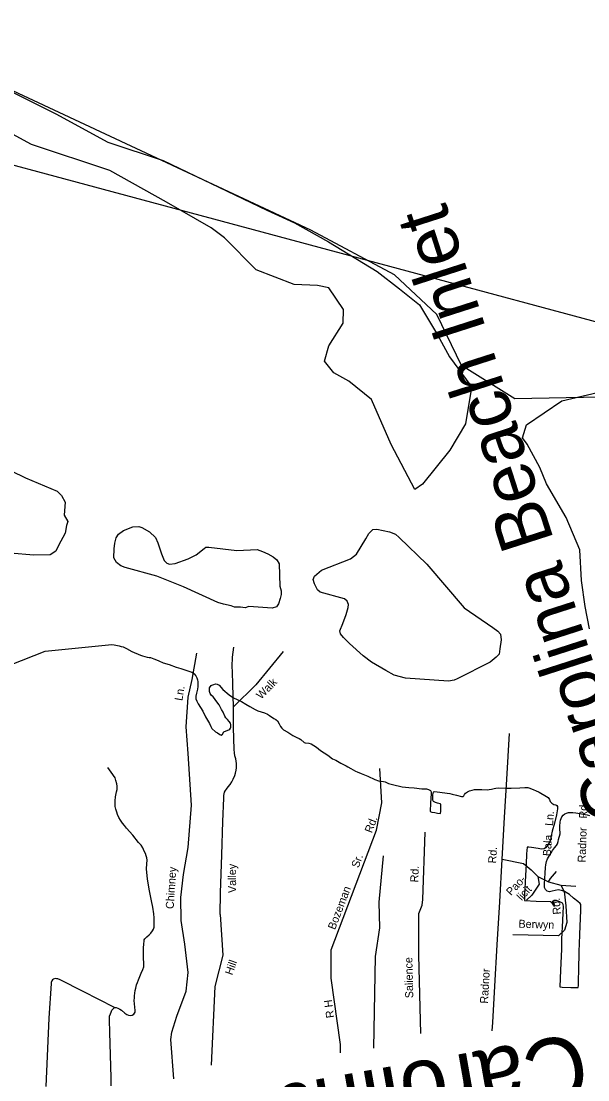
# Model space of a CAD drawing. Extents: x 2308163 to 2335412, y -96774 to 125428.
# Drawn here: x 2326217.9 to 2326312.3, y 123164.6 to 123340.9 of the extents above; entities that cross this region are included whole.
import ezdxf

# ---------------------------------------------------------------- set-up
doc = ezdxf.new("R2010")
doc.units = 0
for name, color, linetype in [('Old_Level_10', 7, 'Continuous'), ('Old_Level_21', 7, 'Continuous'), ('Old_Level_35', 7, 'Continuous'), ('Old_Level_52', 7, 'Continuous'), ('Old_Level_6', 7, 'Continuous'), ('Old_Level_60', 7, 'Continuous'), ('Old_Level_61', 7, 'Continuous'), ('Old_Level_63', 7, 'Continuous')]:
    doc.layers.add(name, color=color, linetype=linetype)

msp = doc.modelspace()

# ---------------------------------------------------------------- linework, layer by layer
at = {"layer": 'Old_Level_35'}
for p, q in [((2326271.09, 123170.5), (2326269.51, 123181.52)), ((2326296.37, 123172.76), (2326296.45, 123174.17)), ((2326271.09, 123169.11), (2326271.09, 123170.5)), ((2326232.91, 123163.62), (2326232.87, 123165))]:
    msp.add_line(p, q, dxfattribs=at)
for points in [[(2326246.36, 123231.28), (2326247.13, 123235.68)], [(2326253.29, 123226.74), (2326253.14, 123230.41), (2326253.07, 123232.56), (2326253.04, 123233.45), (2326253.08, 123234.96), (2326253.33, 123236.66)], [(2326261.52, 123235.93), (2326256.96, 123230.39), (2326253.29, 123226.74)], [(2326243.33, 123164.79), (2326242.85, 123171.32), (2326242.99, 123172.56), (2326243.81, 123175.21), (2326245.39, 123179.38), (2326245.71, 123182.46), (2326245.15, 123187.22), (2326244.56, 123191.15), (2326244.49, 123194.97), (2326244.93, 123198.77), (2326245.7, 123203.27), (2326246.26, 123210.36), (2326245.73, 123218.94), (2326245.36, 123223.38), (2326245.74, 123228.31), (2326246.36, 123231.28)], [(2326251.03, 123192.12), (2326251.12, 123195.74), (2326251.32, 123202.08), (2326251.49, 123207.64), (2326251.67, 123211.49), (2326251.67, 123211.95), (2326251.7, 123212.22), (2326251.77, 123212.51), (2326251.94, 123212.79), (2326252.12, 123213.03), (2326252.4, 123213.39), (2326252.7, 123213.79), (2326252.98, 123214.22), (2326253.21, 123214.66), (2326253.46, 123215.27), (2326253.59, 123215.68), (2326253.7, 123216.15), (2326253.76, 123216.57), (2326253.76, 123216.91), (2326253.76, 123217.26), (2326253.7, 123217.69), (2326253.63, 123218.03), (2326253.5, 123218.58), (2326253.43, 123219.07), (2326253.37, 123219.63), (2326253.29, 123223.25), (2326253.29, 123226.74)], [(2326296.45, 123174.17), (2326296.8, 123180.2), (2326297.2, 123187.11), (2326297.63, 123194.25), (2326298.04, 123201.35), (2326298.41, 123208.29), (2326298.81, 123214.66), (2326299.23, 123222.26)], [(2326233.42, 123176.66), (2326233.54, 123176.66), (2326233.71, 123176.66), (2326233.99, 123176.56), (2326234.35, 123176.39), (2326234.59, 123176.18), (2326235.19, 123175.72), (2326235.51, 123175.51), (2326235.77, 123175.37), (2326236.1, 123175.34), (2326236.4, 123175.36), (2326236.65, 123175.53), (2326236.77, 123175.68), (2326236.86, 123175.89), (2326236.91, 123176.13), (2326236.74, 123177.84), (2326236.75, 123178.28), (2326236.76, 123178.61), (2326236.91, 123179.46), (2326237, 123179.86), (2326237.13, 123180.43), (2326237.27, 123180.83), (2326237.44, 123181.28), (2326237.65, 123181.8), (2326237.9, 123182.35), (2326238.17, 123182.97), (2326238.31, 123183.41), (2326238.35, 123183.77), (2326238.32, 123184.1), (2326238.3, 123184.79), (2326238.27, 123185.53), (2326238.3, 123186.5), (2326238.32, 123187.31), (2326238.36, 123187.63), (2326238.4, 123187.89), (2326238.51, 123188.1), (2326238.83, 123188.43), (2326239.2, 123188.75), (2326239.5, 123189.03), (2326239.75, 123189.39), (2326239.93, 123189.72), (2326240.03, 123190.05), (2326240.06, 123190.48), (2326240.07, 123190.92), (2326240.04, 123191.58), (2326239.98, 123192.23), (2326239.81, 123193.37), (2326239.58, 123194.43), (2326239.3, 123196.06), (2326238.94, 123198.03), (2326238.86, 123198.65), (2326238.81, 123199.13), (2326238.79, 123199.74), (2326238.84, 123200.58), (2326238.86, 123201.2), (2326238.82, 123201.56), (2326238.71, 123201.93), (2326238.58, 123202.27), (2326238.4, 123202.67), (2326238.14, 123203.21), (2326237.86, 123203.66), (2326237.46, 123204.15), (2326236.52, 123205.36), (2326235.45, 123206.52), (2326235.09, 123206.93), (2326234.78, 123207.35), (2326234.43, 123207.84), (2326234.18, 123208.28), (2326233.95, 123208.77), (2326233.81, 123209.16), (2326233.66, 123209.69), (2326233.58, 123210.14), (2326233.55, 123210.47), (2326233.55, 123211.08), (2326233.62, 123211.73), (2326233.8, 123212.54), (2326233.88, 123212.94), (2326233.9, 123213.48), (2326233.84, 123213.88), (2326233.69, 123214.45), (2326233.54, 123214.9), (2326232.87, 123215.81), (2326232.32, 123216.59)], [(2326269.51, 123181.52), (2326269.55, 123186.23), (2326277.06, 123206.18), (2326277.96, 123210.73), (2326277.66, 123216.44)], [(2326284.45, 123172.32), (2326284.14, 123185.35), (2326284.15, 123192.28), (2326284.66, 123193.67), (2326284.81, 123194.66), (2326285.2, 123205.85)], [(2326276.64, 123169.9), (2326276.91, 123185.13), (2326277.61, 123189.92), (2326277.52, 123194.21), (2326278.25, 123201.93)], [(2326298.04, 123201.35), (2326301.59, 123200.65), (2326302.84, 123199.55), (2326303.98, 123198.46), (2326304.17, 123197.16), (2326302.93, 123195.33), (2326302.08, 123194.53)], [(2326303.98, 123198.46), (2326305.71, 123197.58), (2326306.08, 123198.15), (2326307.04, 123199.31)], [(2326307.81, 123197.04), (2326308.36, 123195.96), (2326308.63, 123193.6), (2326308.77, 123190.78), (2326308.37, 123189.51), (2326307.4, 123188.6), (2326299.77, 123188.75)], [(2326305.71, 123197.58), (2326307.81, 123197.04), (2326310.27, 123196.83)], [(2326251.03, 123192.12), (2326251.48, 123185.35), (2326250.16, 123180.14), (2326249.56, 123167.05)], [(2326233.42, 123176.66), (2326228.25, 123179.34), (2326224.39, 123181.23), (2326223.99, 123181.4), (2326223.79, 123181.44), (2326223.55, 123181.46), (2326223.31, 123181.39), (2326223.13, 123181.25), (2326223.01, 123181.09), (2326222.91, 123180.83), (2326222.91, 123180.65), (2326222.49, 123174.89), (2326222.02, 123163.5)], [(2326232.87, 123165), (2326232.67, 123172.49), (2326232.6, 123174.57), (2326232.61, 123174.93), (2326232.63, 123175.23), (2326232.75, 123175.62), (2326232.87, 123175.9), (2326233.01, 123176.18), (2326233.42, 123176.66)]]:
    msp.add_lwpolyline(points, dxfattribs=at)
at = {"layer": 'Old_Level_52'}
msp.add_lwpolyline([(2326352.46, 123278.37), (2326344.49, 123279.39), (2326334.11, 123277.47), (2326314.41, 123278.3), (2326300.12, 123278.02), (2326291.22, 123283.57), (2326287.11, 123292.06), (2326280.06, 123298.67), (2326266.15, 123306.08), (2326194.23, 123339.67), (2326117.56, 123374.58), (2325996.97, 123429.09), (2325967.84, 123440.3), (2325941.49, 123450.31)], dxfattribs=at)
at = {"layer": 'Old_Level_60'}
for points in [[(2326127.66, 123373.96), (2326132.4, 123371.8), (2326136.14, 123367.53), (2326140.13, 123366.07), (2326143.93, 123363.85), (2326143.86, 123361.92), (2326157.43, 123357.03), (2326182.68, 123345.67), (2326202.81, 123335.85), (2326223.69, 123325.46), (2326232.34, 123320.74), (2326241.56, 123317.67)], [(2326242.1, 123310.74), (2326232.69, 123316.04), (2326219.63, 123320.35), (2326204.37, 123328.62), (2326193.35, 123332.04), (2326192.88, 123333.43), (2326189.59, 123335.76), (2326186.26, 123336.7), (2326182.89, 123336.82), (2326179.29, 123337.5), (2326177.6, 123341.14)], [(2326241.56, 123317.67), (2326258.84, 123309.4), (2326263.45, 123307.33), (2326269.08, 123304.16), (2326277.2, 123299.21), (2326280.93, 123296.32), (2326284.24, 123293.65), (2326287.26, 123288.66), (2326289.26, 123284.98), (2326292.81, 123280.16)], [(2326292.81, 123280.16), (2326292.91, 123279.91), (2326291.88, 123273.83), (2326289.28, 123269.43), (2326284.76, 123263.8), (2326283.44, 123262.88), (2326279.52, 123270.41), (2326276.24, 123277.92), (2326272.49, 123280.95), (2326269.96, 123282.32), (2326268.42, 123284.3), (2326269.15, 123286.85), (2326271.53, 123290.63), (2326271.61, 123292.88), (2326269.16, 123296.5), (2326267.24, 123296.89), (2326263.39, 123297.02), (2326257.04, 123299.49), (2326251.75, 123304.82), (2326249.56, 123306.5), (2326242.1, 123310.74)], [(2326302.05, 123273.67), (2326307.94, 123277.66), (2326313.91, 123279.08), (2326320.04, 123279.28), (2326325.92, 123277.85), (2326333.48, 123278), (2326338.39, 123278.44), (2326343.96, 123279.89), (2326346.61, 123279.79), (2326350.86, 123278.63), (2326397.35, 123255.76)], [(2326312.56, 123239.69), (2326311.86, 123243.45), (2326311.2, 123247.75), (2326310.96, 123252.86), (2326308.7, 123258.25), (2326305.42, 123263.87), (2326304.29, 123266.56), (2326302.18, 123270.47), (2326301.39, 123271.53), (2326302.05, 123273.67)], [(2326216.12, 123233.73), (2326221.9, 123236.01), (2326233, 123237.09), (2326233.41, 123237.03), (2326234.21, 123236.87), (2326234.57, 123236.78), (2326234.89, 123236.68), (2326235.46, 123236.44), (2326236.34, 123235.92), (2326237.79, 123235.3), (2326238.1, 123235.2), (2326238.89, 123234.98), (2326239.2, 123234.92), (2326239.43, 123234.91), (2326240.02, 123234.73), (2326240.42, 123234.55), (2326240.8, 123234.35), (2326241.53, 123234.05), (2326242.56, 123233.74), (2326243.73, 123233.32), (2326244.48, 123233.12), (2326245.31, 123232.83), (2326245.68, 123232.73), (2326246.31, 123232.49), (2326246.48, 123232.4), (2326246.72, 123232.19), (2326246.97, 123231.86), (2326247.13, 123231.54), (2326247.26, 123231.19), (2326247.31, 123230.89), (2326247.3, 123230.1), (2326247.25, 123229.64), (2326247.1, 123229.01), (2326247.01, 123228.48), (2326246.99, 123228.05), (2326247.15, 123227.64), (2326247.39, 123227.21), (2326248.13, 123225.97), (2326248.59, 123225.07), (2326249.29, 123223.92), (2326249.49, 123223.45), (2326249.68, 123223.09), (2326250.29, 123222.54), (2326250.62, 123222.36), (2326250.97, 123222.12), (2326251.22, 123222.01), (2326251.41, 123222.19)], [(2326251.41, 123222.19), (2326251.67, 123222.53), (2326252.04, 123222.73), (2326252.46, 123222.89), (2326252.64, 123223), (2326252.77, 123223.16), (2326252.83, 123223.31), (2326252.82, 123223.71), (2326252.74, 123224.02), (2326252.53, 123224.3), (2326252.26, 123224.6), (2326252.01, 123224.91), (2326251.84, 123225.18), (2326251.54, 123225.84), (2326251.29, 123226.26), (2326250.85, 123227.07), (2326250.32, 123227.76), (2326250.11, 123228.08), (2326249.86, 123228.39), (2326249.57, 123228.68), (2326249.35, 123228.93), (2326249.25, 123229.28), (2326249.24, 123229.59), (2326249.28, 123229.87), (2326249.57, 123230.29), (2326249.65, 123230.34), (2326249.96, 123230.46), (2326250.26, 123230.52), (2326250.57, 123230.47), (2326250.87, 123230.31), (2326251.48, 123229.63), (2326252.53, 123228.71), (2326252.91, 123228.43), (2326253.28, 123228.2), (2326254.57, 123227.62), (2326255.31, 123227.16), (2326255.99, 123226.78), (2326256.85, 123226.27), (2326257.3, 123226.07), (2326258.44, 123225.72), (2326258.92, 123225.48), (2326259.28, 123225.26), (2326259.97, 123224.78), (2326260.31, 123224.58), (2326260.61, 123224.37), (2326260.87, 123223.88), (2326261.07, 123223.45), (2326261.3, 123223.17), (2326261.6, 123222.9), (2326262.3, 123222.49), (2326263.16, 123221.95), (2326263.82, 123221.61), (2326264.18, 123221.45), (2326264.48, 123221.29), (2326265.03, 123220.77), (2326265.19, 123220.7), (2326265.79, 123220.66), (2326266.21, 123220.53), (2326266.67, 123220.29), (2326267.07, 123220), (2326267.74, 123219.46), (2326268.95, 123218.65), (2326269.75, 123218.07), (2326270.29, 123217.81), (2326271.12, 123217.32), (2326272.01, 123216.88), (2326272.33, 123216.74), (2326272.81, 123216.47), (2326273.56, 123216.01), (2326273.84, 123215.87), (2326274.5, 123215.63), (2326275.64, 123215.17), (2326276.8, 123214.63), (2326277.43, 123214.42), (2326277.84, 123214.33), (2326278.22, 123214.29), (2326278.5, 123214.23), (2326279.06, 123213.96), (2326279.74, 123213.76), (2326281.38, 123213.42), (2326282.48, 123213.29), (2326283.37, 123213.23), (2326284.65, 123213.07), (2326285.41, 123213.04), (2326285.77, 123212.94), (2326286.06, 123212.78), (2326286.16, 123212.58), (2326286.17, 123212.23), (2326286.06, 123210.71), (2326286.01, 123209.29), (2326286.31, 123209.17), (2326286.81, 123209.11), (2326287.25, 123209), (2326287.73, 123208.95), (2326287.77, 123209.33), (2326287.79, 123210.18), (2326287.78, 123210.5), (2326287.69, 123210.56), (2326287.23, 123210.67)], [(2326287.23, 123210.67), (2326286.91, 123210.77), (2326286.55, 123210.96), (2326286.47, 123211.17), (2326286.47, 123211.59), (2326286.49, 123212.06), (2326286.58, 123212.53), (2326286.7, 123212.62), (2326287.19, 123212.58), (2326289.27, 123212.28), (2326289.68, 123212.19), (2326290.39, 123211.99), (2326291.22, 123211.79), (2326291.53, 123211.8), (2326291.64, 123211.92), (2326291.72, 123212.12), (2326291.92, 123212.35), (2326292.23, 123212.57), (2326292.59, 123212.73), (2326292.99, 123212.85), (2326293.39, 123212.94), (2326293.79, 123212.97), (2326294.63, 123212.97), (2326295.54, 123212.9), (2326295.86, 123212.93), (2326296.22, 123213.03), (2326296.67, 123213.12), (2326296.98, 123213.2), (2326297.45, 123213.23), (2326298.69, 123213.15), (2326299.51, 123213.17), (2326300.97, 123213.23), (2326301.79, 123213.31), (2326302.26, 123213.29), (2326302.64, 123213.18), (2326303.27, 123212.9), (2326303.56, 123212.76), (2326304.2, 123212.49), (2326305.39, 123211.8), (2326305.65, 123211.61), (2326305.88, 123211.31), (2326306.02, 123210.97), (2326306.28, 123210.69), (2326306.63, 123210.48), (2326306.97, 123210.38), (2326307.14, 123210.3), (2326307.24, 123210.11), (2326307.24, 123209.75), (2326307.08, 123208.74), (2326306.74, 123207.35), (2326306.36, 123206.01), (2326306.17, 123205.21), (2326306.05, 123204.55), (2326305.93, 123204.22), (2326305.72, 123203.89)], [(2326305.72, 123203.89), (2326305.22, 123203.22), (2326305.02, 123203.05), (2326304.54, 123203.04), (2326304.02, 123203.1), (2326302.9, 123203.28), (2326302.44, 123203.33), (2326302.17, 123203.34), (2326302.1, 123202.82), (2326302.05, 123202.26), (2326302, 123200.52), (2326301.92, 123198.64), (2326301.85, 123197.5), (2326301.81, 123196.41), (2326301.76, 123195.46), (2326301.73, 123194.47), (2326303.68, 123194.34), (2326306.06, 123194.28), (2326306.21, 123194.21), (2326306.57, 123193.63), (2326306.64, 123193.55), (2326306.81, 123193.63), (2326306.59, 123194), (2326306.44, 123194.3), (2326306.43, 123194.38), (2326306.68, 123194.55), (2326307, 123194.51), (2326307.69, 123194.23), (2326307.98, 123194.08), (2326308.1, 123193.87), (2326308.16, 123193.39), (2326308.14, 123192.44), (2326308.05, 123191.11), (2326307.92, 123188.01), (2326307.89, 123186.38), (2326307.72, 123182.84), (2326307.64, 123180.1), (2326308.02, 123180.04), (2326309.44, 123179.96), (2326310.67, 123179.96), (2326310.75, 123180.33), (2326310.78, 123183.76), (2326310.81, 123185.03), (2326310.84, 123186.11), (2326310.9, 123187.21), (2326310.94, 123188.86), (2326311.1, 123192.8), (2326311.11, 123193.58), (2326311.1, 123193.79), (2326311.03, 123193.96), (2326310.62, 123194.3), (2326309.92, 123194.83), (2326309.2, 123195.45), (2326308.41, 123195.97), (2326307.92, 123196.12), (2326307.35, 123196.22), (2326306.82, 123196.15), (2326306.36, 123196.03), (2326305.87, 123195.93), (2326305.51, 123196.02), (2326305.22, 123196.31), (2326305.08, 123196.65), (2326305.08, 123197.24), (2326305.11, 123198.13), (2326305.18, 123199.01), (2326305.22, 123199.94), (2326305.27, 123200.39), (2326305.38, 123200.94), (2326305.56, 123201.43), (2326306.17, 123202.38), (2326306.42, 123202.8), (2326306.75, 123203.24), (2326307.06, 123203.6), (2326307.25, 123203.93), (2326307.35, 123204.27), (2326307.39, 123204.6), (2326307.67, 123205.56), (2326307.68, 123205.86), (2326307.64, 123206.23), (2326307.63, 123206.85), (2326307.67, 123207.52), (2326307.73, 123207.85), (2326307.96, 123208.4), (2326308.16, 123208.67), (2326308.44, 123208.91), (2326308.74, 123209.03), (2326309.07, 123209.1), (2326309.38, 123209.12), (2326309.78, 123209.1), (2326310.26, 123209.05), (2326312.19, 123208.73), (2326312.58, 123208.62)]]:
    msp.add_lwpolyline(points, dxfattribs=at)
at = {"layer": 'Old_Level_61'}
for points in [[(2326213.65, 123267.24), (2326218.62, 123264.86), (2326223.87, 123262.62), (2326224.61, 123261.89), (2326225.24, 123260.8), (2326225.05, 123258.64), (2326225.66, 123257.55)], [(2326225.66, 123257.55), (2326225.47, 123256.89), (2326225.24, 123255.65), (2326224.1, 123253.6), (2326223.65, 123252.66), (2326222.71, 123252.01), (2326219.99, 123251.96), (2326216.07, 123252.29)], [(2326261.22, 123245.44), (2326261.02, 123244.77), (2326260.75, 123243.89), (2326260.41, 123243.39), (2326259.71, 123243.13), (2326255.83, 123243.41), (2326255.22, 123243.22), (2326254.45, 123243.29), (2326253.44, 123243.31), (2326252.86, 123243.51), (2326251.58, 123243.8), (2326250.63, 123244.11), (2326244.94, 123246.68), (2326240.47, 123248.5), (2326235.21, 123249.92), (2326234.52, 123250.2), (2326233.77, 123250.77), (2326233.32, 123251.5), (2326233.37, 123253.02), (2326233.52, 123253.96), (2326233.73, 123254.87), (2326234.1, 123255.49), (2326234.93, 123256.07), (2326236.47, 123256.68), (2326237.51, 123256.75), (2326238.02, 123256.6), (2326239.25, 123255.85), (2326240.26, 123254.93), (2326240.66, 123254.01), (2326241.26, 123252.2), (2326241.7, 123251.07), (2326242.16, 123250.64), (2326242.61, 123250.5), (2326243.53, 123250.59), (2326245.7, 123251.34), (2326247.06, 123252), (2326248.35, 123253.06), (2326248.66, 123253.31), (2326249.18, 123253.31), (2326253.82, 123252.73), (2326257.19, 123252.9), (2326258.09, 123252.59), (2326258.98, 123252.2), (2326259.89, 123251.7), (2326260.5, 123251.17), (2326260.87, 123250.55), (2326261, 123246.8), (2326261.18, 123246.06), (2326261.22, 123245.44)], [(2326297.87, 123237.89), (2326297.64, 123236.38), (2326297.49, 123235.46), (2326296.99, 123235.01), (2326295.99, 123234.17), (2326290.54, 123231.38), (2326290.02, 123231.14), (2326289.08, 123231), (2326281.93, 123231.5), (2326280.05, 123232.01), (2326278.66, 123232.75), (2326276.27, 123234.13), (2326274.85, 123235.22), (2326272.6, 123237.24), (2326271.57, 123238.24), (2326271.08, 123238.89), (2326270.98, 123239.36), (2326271.5, 123240.59), (2326272.02, 123242.09), (2326272.34, 123243.25), (2326272.43, 123243.75), (2326272.19, 123244.29), (2326271.76, 123244.7), (2326267.71, 123245.83), (2326267.28, 123246.2), (2326266.73, 123247.22), (2326266.56, 123247.9), (2326266.76, 123248.49), (2326267.91, 123249.49), (2326272.73, 123251.34), (2326273.75, 123252.12), (2326275.33, 123254.69), (2326275.83, 123255.6), (2326276.48, 123256.24), (2326277.13, 123256.28), (2326279.23, 123255.86), (2326280.27, 123255.48), (2326280.84, 123254.91), (2326285.48, 123250.47), (2326291.71, 123243.21), (2326296.46, 123239.95), (2326297.31, 123239.33), (2326297.76, 123238.81), (2326297.87, 123237.89)]]:
    msp.add_lwpolyline(points, dxfattribs=at)
at = {"layer": 'Old_Level_63'}
msp.add_lwpolyline([(2326475.8, 123239.36), (2326422.14, 123261.61), (2325934.09, 123392.92)], dxfattribs=at)

# ---------------------------------------------------------------- texts
at = {"layer": 'Old_Level_10'}
for s, height, rotation, p in [('Walk', 1.333, 45.3872, (2326257.86, 123227.89)), ('Ln.', 1.333, 80.1858, (2326244.73, 123227.65)), ('Bala   Ln.', 1.333, 85.7542, (2326306.1, 123201.81)), ('Radnor   Rd.', 1.3328, 88.1523, (2326311.91, 123200.78)), ('Bozeman       Sr.        Rd.', 1.3328, 69.1948, (2326270.17, 123189.5)), ('Rd.', 1.333, 86.9357, (2326297, 123200.62)), ('Valley', 1.333, 90.4143, (2326253.71, 123195.72)), ('Chimney', 1.333, 86.2486, (2326243.29, 123193.02)), ('Rd.', 1.333, 87.6086, (2326284.02, 123197.46)), ('Pao-', 1.333, 46.9069, (2326299.5, 123195.17)), ('licit', 1.333, 46.9069, (2326301.27, 123194.34)), ('Rd.', 1.333, 94.3165, (2326307.81, 123192.18)), ('Berwyn', 1.333, 358.1695, (2326300.72, 123189.94)), ('Hill ', 1.333, 70.5702, (2326253.06, 123181.94)), ('Salience', 1.333, 91.3925, (2326283.21, 123178.21)), ('Radnor', 1.333, 86.7192, (2326295.63, 123177.27)), ('R H', 1.333, 97.6871, (2326270.05, 123174.98))]:
    msp.add_text(s, height=height, rotation=rotation, dxfattribs=at).set_placement(p)
at = {"layer": 'Old_Level_21'}
msp.add_text('Carolina Beach Inlet', height=8.8541, rotation=107.8345, dxfattribs=at).set_placement((2326321.21, 123209.33))
at = {"layer": 'Old_Level_6'}
msp.add_text('Carolina', height=10.796, rotation=190.02, dxfattribs=at).set_placement((2326311.15, 123172.45))

doc.saveas('drawing.dxf')
